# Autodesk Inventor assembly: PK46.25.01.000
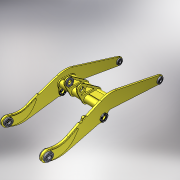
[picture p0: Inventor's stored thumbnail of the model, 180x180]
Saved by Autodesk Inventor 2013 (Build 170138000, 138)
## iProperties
Created: 2005-04
Part Number: PK46.25.01.000
Document SubType Name: Assembly
Designer: salex
Manufacturer: Standard
Standards Organization: Custom
Author: salex
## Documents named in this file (8)
- C:\Product Design Suite 2013 Test Drive\Dynamic Simulation\Workspace\Assy, Chassis, Front\PK46.25.01.000.iam
- C:\Product Design Suite 2013 Test Drive\Dynamic Simulation\Workspace\Assy, Chassis, Front\PK46.25.01.011.ipt
- C:\Product Design Suite 2013 Test Drive\Dynamic Simulation\Workspace\Assy, Chassis, Front\PK46.25.01.013.ipt
- C:\Product Design Suite 2013 Test Drive\Dynamic Simulation\Workspace\Assy, Chassis, Front\PK46.25.01.014.ipt
- C:\Product Design Suite 2013 Test Drive\Dynamic Simulation\Workspace\Assy, Chassis, Front\PK46.25.01.015.ipt
- C:\Product Design Suite 2013 Test Drive\Dynamic Simulation\Workspace\Assy, Chassis, Front\M10-6H.5.019(S16).ipt
- C:\Product Design Suite 2013 Test Drive\Dynamic Simulation\Workspace\Assy, Chassis, Front\10.65G.019.ipt
- C:\Product Design Suite 2013 Test Drive\Dynamic Simulation\Workspace\Assy, Chassis, Front\PK46.25.01.010.iam
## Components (35 placed, 7 different names)
1. PK46.25.01.010:1 [sub-assembly] — Вставка:1, Вставка:2, Вставка:3, Вставка:4, Вставка:5, Вставка:6, Вставка:7, Вставка:8, Вставка:13, Вставка:14, Вставка:15, Вставка:16, Совмещение:1, Совмещение:2, Совмещение:3, Совмещение:4
2. PK46.25.01.011:1 — Вставка:2
3. PK46.25.01.011:2 — Вставка:1
4. PK46.25.01.011:3 — Вставка:7
5. PK46.25.01.011:4 — Вставка:8
6. PK46.25.01.011:5 — Вставка:6
7. PK46.25.01.011:6 — Вставка:5
8. PK46.25.01.011:7 — Вставка:4
9. PK46.25.01.011:8 — Вставка:3
10. PK46.25.01.013:1 — Вставка:9
11. PK46.25.01.013:2 — Вставка:10
12. PK46.25.01.013:3 — Вставка:11
13. PK46.25.01.013:4 — Вставка:12
14. PK46.25.01.014:1 — Вставка:9, Вставка:13, Совмещение:3
15. PK46.25.01.014:2 — Вставка:10, Вставка:15, Совмещение:4, Вставка:34, Вставка:33, Вставка:32, Вставка:31, Вставка:30, Вставка:29
16. PK46.25.01.014:3 — Вставка:11, Вставка:14, Совмещение:2
17. PK46.25.01.014:4 — Вставка:12, Вставка:16, Совмещение:1, Вставка:23, Вставка:24, Вставка:25, Вставка:26, Вставка:27, Вставка:28
18. PK46.25.01.015:1 — Вставка:23
19. PK46.25.01.015:2 — Вставка:24
20. PK46.25.01.015:3 — Вставка:25
21. PK46.25.01.015:4 — Вставка:26
22. PK46.25.01.015:5 — Вставка:27
23. PK46.25.01.015:6 — Вставка:28
24. M10-6H.5.019(S16):1 — Вставка:22
25. M10-6H.5.019(S16):2 — Вставка:21
26. M10-6H.5.019(S16):3 — Вставка:20
27. M10-6H.5.019(S16):4 — Вставка:19
28. M10-6H.5.019(S16):5 — Вставка:18
29. M10-6H.5.019(S16):6 — Вставка:17
30. 10.65G.019:1 — Вставка:22, Вставка:34
31. 10.65G.019:2 — Вставка:21, Вставка:33
32. 10.65G.019:3 — Вставка:20, Вставка:32
33. 10.65G.019:4 — Вставка:19, Вставка:31
34. 10.65G.019:5 — Вставка:18, Вставка:30
35. 10.65G.019:6 — Вставка:17, Вставка:29
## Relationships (38: Insert 34, Mate 4)
- Вставка:1 [Insert]: PK46.25.01.010:1 ↔ PK46.25.01.011:2
- Вставка:2 [Insert]: PK46.25.01.010:1 ↔ PK46.25.01.011:1
- Вставка:3 [Insert]: PK46.25.01.010:1 ↔ PK46.25.01.011:8
- Вставка:4 [Insert]: PK46.25.01.010:1 ↔ PK46.25.01.011:7
- Вставка:5 [Insert]: PK46.25.01.010:1 ↔ PK46.25.01.011:6
- Вставка:6 [Insert]: PK46.25.01.010:1 ↔ PK46.25.01.011:5
- Вставка:7 [Insert]: PK46.25.01.010:1 ↔ PK46.25.01.011:3
- Вставка:8 [Insert]: PK46.25.01.010:1 ↔ PK46.25.01.011:4
- Вставка:9 [Insert]: PK46.25.01.013:1 ↔ PK46.25.01.014:1
- Вставка:10 [Insert]: PK46.25.01.013:2 ↔ PK46.25.01.014:2
- Вставка:11 [Insert]: PK46.25.01.013:3 ↔ PK46.25.01.014:3
- Вставка:12 [Insert]: PK46.25.01.013:4 ↔ PK46.25.01.014:4
- Вставка:13 [Insert]: PK46.25.01.010:1 ↔ PK46.25.01.014:1
- Вставка:14 [Insert]: PK46.25.01.010:1 ↔ PK46.25.01.014:3
- Вставка:15 [Insert]: PK46.25.01.010:1 ↔ PK46.25.01.014:2
- Вставка:16 [Insert]: PK46.25.01.010:1 ↔ PK46.25.01.014:4
- Совмещение:1 [Mate]: PK46.25.01.010:1 ↔ PK46.25.01.014:4
- Совмещение:2 [Mate]: PK46.25.01.010:1 ↔ PK46.25.01.014:3
- Совмещение:3 [Mate]: PK46.25.01.010:1 ↔ PK46.25.01.014:1
- Совмещение:4 [Mate]: PK46.25.01.010:1 ↔ PK46.25.01.014:2
- Вставка:17 [Insert]: M10-6H.5.019(S16):6 ↔ 10.65G.019:6
- Вставка:18 [Insert]: M10-6H.5.019(S16):5 ↔ 10.65G.019:5
- Вставка:19 [Insert]: M10-6H.5.019(S16):4 ↔ 10.65G.019:4
- Вставка:20 [Insert]: M10-6H.5.019(S16):3 ↔ 10.65G.019:3
- Вставка:21 [Insert]: M10-6H.5.019(S16):2 ↔ 10.65G.019:2
- Вставка:22 [Insert]: M10-6H.5.019(S16):1 ↔ 10.65G.019:1
- Вставка:23 [Insert]: PK46.25.01.014:4 ↔ PK46.25.01.015:1
- Вставка:24 [Insert]: PK46.25.01.014:4 ↔ PK46.25.01.015:2
- Вставка:25 [Insert]: PK46.25.01.014:4 ↔ PK46.25.01.015:3
- Вставка:26 [Insert]: PK46.25.01.014:4 ↔ PK46.25.01.015:4
- Вставка:27 [Insert]: PK46.25.01.014:4 ↔ PK46.25.01.015:5
- Вставка:28 [Insert]: PK46.25.01.014:4 ↔ PK46.25.01.015:6
- Вставка:34 [Insert]: PK46.25.01.014:2 ↔ 10.65G.019:1
- Вставка:33 [Insert]: PK46.25.01.014:2 ↔ 10.65G.019:2
- Вставка:32 [Insert]: PK46.25.01.014:2 ↔ 10.65G.019:3
- Вставка:31 [Insert]: PK46.25.01.014:2 ↔ 10.65G.019:4
- Вставка:30 [Insert]: PK46.25.01.014:2 ↔ 10.65G.019:5
- Вставка:29 [Insert]: PK46.25.01.014:2 ↔ 10.65G.019:6
